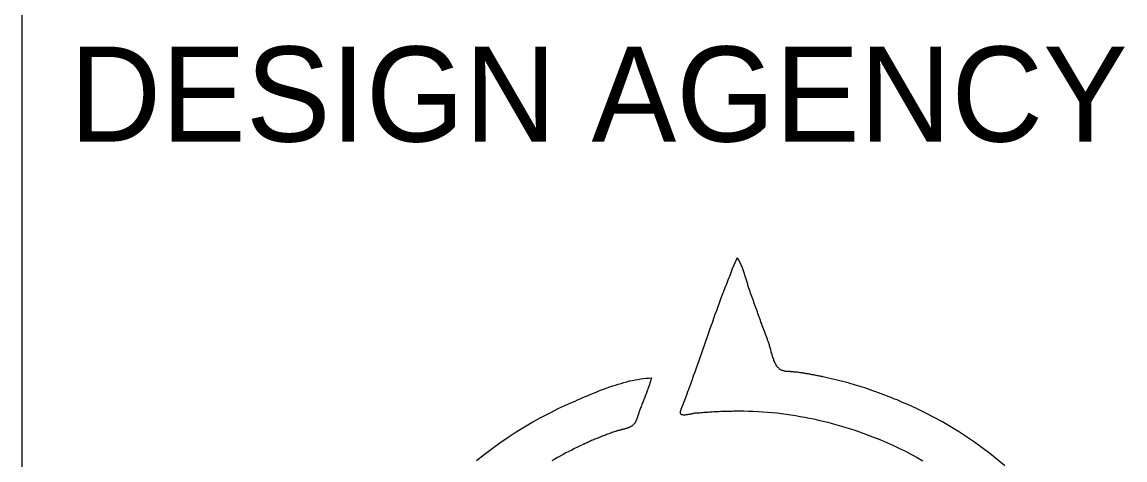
# Model space of a CAD drawing. Extents: x -1.1 to 34, y 0 to 22.
# Drawn here: x 32 to 33.162, y 4.015 to 4.476 of the extents above; entities that cross this region are included whole.
import ezdxf

# ---------------------------------------------------------------- set-up
doc = ezdxf.new("R2010")
doc.units = 0
doc.layers.add('BR_X_SV_Abut', color=7, linetype='Continuous')
doc.layers.add('RW_X_CL', color=7, linetype='Continuous')

msp = doc.modelspace()

# ---------------------------------------------------------------- linework, layer by layer
at = {"layer": 'BR_X_SV_Abut'}
for points in [[(32.7532, 4.2277), (32.7515, 4.2238), (32.7498, 4.2199), (32.7481, 4.216), (32.7466, 4.212), (32.745, 4.208), (32.7434, 4.2041), (32.7418, 4.2001), (32.7403, 4.1961), (32.7387, 4.1921), (32.7372, 4.1881), (32.7357, 4.1841), (32.7342, 4.1801), (32.7328, 4.176), (32.7313, 4.172), (32.7298, 4.168), (32.7284, 4.1639), (32.7271, 4.1599), (32.7256, 4.1558), (32.7241, 4.1518), (32.7227, 4.1478), (32.7214, 4.1436), (32.7199, 4.1396), (32.7184, 4.1355), (32.7171, 4.1315), (32.7157, 4.1275), (32.7142, 4.1235), (32.7129, 4.1194), (32.7114, 4.1154), (32.71, 4.1114), (32.7085, 4.1074), (32.707, 4.1035)], [(32.7656, 4.1959), (32.7652, 4.1969), (32.7649, 4.1978), (32.7646, 4.1988), (32.7643, 4.1998), (32.764, 4.2009), (32.7637, 4.202), (32.7633, 4.2031), (32.7631, 4.2041), (32.7627, 4.2051), (32.7623, 4.2063), (32.7621, 4.2074), (32.7617, 4.2085), (32.7614, 4.2096), (32.761, 4.2107), (32.7606, 4.2118), (32.7603, 4.2129), (32.7599, 4.214), (32.7595, 4.2151), (32.7592, 4.2161), (32.7587, 4.2172), (32.7583, 4.2182), (32.7578, 4.2193), (32.7575, 4.2203), (32.757, 4.2214), (32.7565, 4.2223), (32.756, 4.2233), (32.7555, 4.2242), (32.7549, 4.2251), (32.7545, 4.226), (32.7538, 4.2268), (32.7532, 4.2277)], [(32.7856, 4.1404), (32.785, 4.1422), (32.7844, 4.144), (32.7837, 4.1457), (32.7831, 4.1475), (32.7823, 4.1493), (32.7817, 4.1512), (32.781, 4.1529), (32.7804, 4.1547), (32.7797, 4.1565), (32.7791, 4.1582), (32.7783, 4.16), (32.7777, 4.1618), (32.777, 4.1637), (32.7764, 4.1654), (32.7758, 4.1672), (32.7751, 4.169), (32.7745, 4.1708), (32.7739, 4.1725), (32.7731, 4.1743), (32.7725, 4.1761), (32.7719, 4.178), (32.7712, 4.1797), (32.7706, 4.1815), (32.77, 4.1833), (32.7694, 4.1851), (32.7686, 4.1869), (32.768, 4.1886), (32.7674, 4.1904), (32.7668, 4.1923), (32.7662, 4.1941), (32.7656, 4.1959)], [(32.7979, 4.1106), (32.7973, 4.1112), (32.7966, 4.1118), (32.796, 4.1124), (32.7954, 4.1131), (32.7949, 4.1138), (32.7943, 4.1147), (32.7939, 4.1156), (32.7934, 4.1165), (32.7929, 4.1175), (32.7925, 4.1186), (32.792, 4.1195), (32.7917, 4.1206), (32.7913, 4.1217), (32.7908, 4.1228), (32.7905, 4.1239), (32.7901, 4.1251), (32.7899, 4.1262), (32.7895, 4.1274), (32.7891, 4.1285), (32.7889, 4.1296), (32.7885, 4.1308), (32.7882, 4.1319), (32.7879, 4.133), (32.7877, 4.1341), (32.7873, 4.135), (32.7871, 4.136), (32.7868, 4.137), (32.7865, 4.138), (32.7862, 4.1388), (32.786, 4.1396), (32.7856, 4.1404)], [(32.5747, 4.0736), (32.5772, 4.0747), (32.5799, 4.0759), (32.5825, 4.077), (32.5852, 4.0782), (32.5879, 4.0794), (32.5907, 4.0806), (32.5934, 4.0818), (32.5962, 4.0829), (32.599, 4.0841), (32.6018, 4.0853), (32.6047, 4.0864), (32.6075, 4.0876), (32.6104, 4.0887), (32.6133, 4.0898), (32.6162, 4.0909), (32.6192, 4.0919), (32.6221, 4.093), (32.6251, 4.0938), (32.628, 4.0948), (32.6309, 4.0956), (32.6338, 4.0965), (32.6369, 4.0973), (32.6398, 4.0981), (32.6427, 4.0987), (32.6456, 4.0993), (32.6485, 4.0998), (32.6514, 4.1002), (32.6543, 4.1007), (32.6572, 4.101), (32.6601, 4.1012), (32.6629, 4.1015)], [(32.6629, 4.1015), (32.6626, 4.1002), (32.6623, 4.0992), (32.6619, 4.0979), (32.6616, 4.0969), (32.6612, 4.0958), (32.6609, 4.0945), (32.6605, 4.0935), (32.6601, 4.0922), (32.6596, 4.0912), (32.6593, 4.0901), (32.6589, 4.0888), (32.6584, 4.0878), (32.6581, 4.0867), (32.6576, 4.0856), (32.6572, 4.0844), (32.6567, 4.0833), (32.6564, 4.0822), (32.6559, 4.0811), (32.6555, 4.0799), (32.655, 4.0788), (32.6546, 4.0777), (32.6542, 4.0766), (32.6537, 4.0754), (32.6532, 4.0743), (32.6529, 4.0732), (32.6524, 4.0721), (32.652, 4.071), (32.6515, 4.0698), (32.6512, 4.0687), (32.6507, 4.0676), (32.6503, 4.0665)], [(32.707, 4.1035), (32.7067, 4.1025), (32.7063, 4.1016), (32.7061, 4.1006), (32.7057, 4.0996), (32.7054, 4.0987), (32.705, 4.0977), (32.7046, 4.0967), (32.7043, 4.0958), (32.7039, 4.0948), (32.7037, 4.0938), (32.7033, 4.0928), (32.7029, 4.092), (32.7026, 4.091), (32.7022, 4.0901), (32.7018, 4.0891), (32.7015, 4.0881), (32.7011, 4.0872), (32.7007, 4.0862), (32.7005, 4.0852), (32.7001, 4.0842), (32.6998, 4.0833), (32.6994, 4.0823), (32.699, 4.0813), (32.6987, 4.0804), (32.6983, 4.0795), (32.698, 4.0785), (32.6976, 4.0776), (32.6972, 4.0766), (32.6969, 4.0756), (32.6965, 4.0747), (32.6963, 4.0737)], [(32.8139, 4.1075), (32.8134, 4.1075), (32.8129, 4.1076), (32.8124, 4.1076), (32.8119, 4.1076), (32.8114, 4.1078), (32.8108, 4.1078), (32.8103, 4.1078), (32.8097, 4.1078), (32.8093, 4.1079), (32.8086, 4.1079), (32.808, 4.1079), (32.8076, 4.1079), (32.807, 4.108), (32.8063, 4.108), (32.8059, 4.1081), (32.8053, 4.1081), (32.8046, 4.1082), (32.8042, 4.1082), (32.8036, 4.1084), (32.8031, 4.1085), (32.8025, 4.1086), (32.802, 4.1087), (32.8015, 4.1089), (32.8009, 4.109), (32.8004, 4.1092), (32.7999, 4.1093), (32.7996, 4.1096), (32.7991, 4.1098), (32.7986, 4.1101), (32.7982, 4.1103), (32.7979, 4.1106)], [(32.8436, 4.1024), (32.8426, 4.1027), (32.8417, 4.1028), (32.8408, 4.103), (32.8398, 4.1033), (32.8388, 4.1034), (32.8379, 4.1036), (32.8369, 4.1038), (32.8359, 4.104), (32.835, 4.1041), (32.8341, 4.1044), (32.8331, 4.1045), (32.8322, 4.1047), (32.8312, 4.1049), (32.8302, 4.1051), (32.8293, 4.1052), (32.8283, 4.1055), (32.8273, 4.1056), (32.8263, 4.1057), (32.8254, 4.1059), (32.8244, 4.1061), (32.8234, 4.1062), (32.8225, 4.1063), (32.8215, 4.1065), (32.8205, 4.1067), (32.8196, 4.1068), (32.8186, 4.1069), (32.8177, 4.107), (32.8168, 4.1072), (32.8158, 4.1073), (32.8148, 4.1074), (32.8139, 4.1075)], [(32.9329, 4.0732), (32.9301, 4.0744), (32.9273, 4.0756), (32.9246, 4.0768), (32.9216, 4.0781), (32.9189, 4.0791), (32.9161, 4.0802), (32.9133, 4.0815), (32.9104, 4.0825), (32.9076, 4.0835), (32.9048, 4.0846), (32.9019, 4.0857), (32.8991, 4.0867), (32.8962, 4.0878), (32.8933, 4.0887), (32.8905, 4.0897), (32.8876, 4.0907), (32.8847, 4.0915), (32.8818, 4.0925), (32.8788, 4.0933), (32.8759, 4.0943), (32.873, 4.0952), (32.8701, 4.096), (32.8672, 4.0967), (32.8643, 4.0976), (32.8614, 4.0983), (32.8584, 4.099), (32.8554, 4.0998), (32.8525, 4.1005), (32.8495, 4.1012), (32.8466, 4.1018), (32.8436, 4.1024)], [(32.4788, 4.0143), (32.4868, 4.0207), (32.495, 4.0269), (32.5034, 4.033), (32.5119, 4.0388), (32.5205, 4.0445), (32.5292, 4.0498), (32.538, 4.055), (32.547, 4.06), (32.5561, 4.0647), (32.5653, 4.0693), (32.5747, 4.0736)], [(32.6503, 4.0665), (32.6501, 4.0661), (32.6499, 4.0656), (32.6498, 4.0652), (32.6496, 4.0647), (32.6495, 4.0642), (32.6493, 4.0638), (32.6492, 4.0631), (32.649, 4.0627), (32.6489, 4.0622), (32.6487, 4.0617), (32.6485, 4.0611), (32.6484, 4.0606), (32.6481, 4.0601), (32.648, 4.0595), (32.6478, 4.059), (32.6476, 4.0585), (32.6474, 4.0579), (32.6473, 4.0574), (32.647, 4.057), (32.6468, 4.0565), (32.6466, 4.056), (32.6463, 4.0555), (32.6461, 4.055), (32.6458, 4.0545), (32.6456, 4.0542), (32.6453, 4.0537), (32.6451, 4.0533), (32.6447, 4.053), (32.6445, 4.0525), (32.6441, 4.0521), (32.6438, 4.0519)], [(32.6963, 4.0737), (32.6961, 4.0735), (32.696, 4.0732), (32.6959, 4.073), (32.6958, 4.0727), (32.6957, 4.0724), (32.6955, 4.0721), (32.6954, 4.0718), (32.6952, 4.0714), (32.695, 4.071), (32.6949, 4.0707), (32.6947, 4.0703), (32.6946, 4.0699), (32.6944, 4.0696), (32.6942, 4.0691), (32.6941, 4.0687), (32.694, 4.0684), (32.6938, 4.068), (32.6937, 4.0675), (32.6936, 4.0671), (32.6935, 4.0668), (32.6935, 4.0664), (32.6933, 4.0661), (32.6933, 4.0657), (32.6932, 4.0653), (32.6932, 4.065), (32.6932, 4.0647), (32.6933, 4.0644), (32.6933, 4.0641), (32.6935, 4.0639), (32.6936, 4.0636), (32.6937, 4.0634)], [(32.7091, 4.0644), (32.7106, 4.0645), (32.7121, 4.0646), (32.7136, 4.0647), (32.7151, 4.0648), (32.7166, 4.065), (32.7181, 4.0651), (32.7195, 4.0652), (32.721, 4.0653), (32.7226, 4.0654), (32.724, 4.0656), (32.7255, 4.0657), (32.7269, 4.0657), (32.7285, 4.0658), (32.73, 4.0659), (32.7314, 4.0659), (32.7329, 4.0661), (32.7344, 4.0661), (32.7359, 4.0662), (32.7374, 4.0662), (32.7388, 4.0663), (32.7404, 4.0663), (32.7418, 4.0663), (32.7433, 4.0664), (32.7449, 4.0664), (32.7463, 4.0664), (32.7478, 4.0664), (32.7494, 4.0665), (32.7508, 4.0665), (32.7523, 4.0665), (32.7538, 4.0665), (32.7553, 4.0665)], [(32.7553, 4.0665), (32.7603, 4.0665), (32.7652, 4.0664), (32.7702, 4.0662), (32.7752, 4.0659), (32.7802, 4.0657), (32.785, 4.0653), (32.79, 4.0648), (32.7949, 4.0644), (32.7999, 4.0638), (32.8048, 4.0631), (32.8097, 4.0624), (32.8146, 4.0617), (32.8196, 4.0608), (32.8244, 4.06), (32.8293, 4.059), (32.8341, 4.0581), (32.839, 4.057), (32.8438, 4.0558), (32.8487, 4.0547), (32.8534, 4.0533), (32.8582, 4.052), (32.863, 4.0507), (32.8678, 4.0492), (32.8725, 4.0477), (32.8773, 4.0462), (32.882, 4.0446), (32.8866, 4.0429), (32.8913, 4.0412), (32.8959, 4.0394), (32.9005, 4.0376), (32.9052, 4.0357)], [(33.0351, 4.0088), (33.0272, 4.0154), (33.0194, 4.0217), (33.0112, 4.0277), (33.0031, 4.0337), (32.9947, 4.0394), (32.9863, 4.045), (32.9777, 4.0503), (32.9689, 4.0553), (32.9601, 4.0601), (32.9511, 4.0647), (32.942, 4.0691), (32.9329, 4.0732)], [(32.6937, 4.0634), (32.694, 4.0633), (32.6942, 4.063), (32.6946, 4.0629), (32.6949, 4.0628), (32.6954, 4.0627), (32.6958, 4.0627), (32.6963, 4.0625), (32.6967, 4.0625), (32.6973, 4.0625), (32.6978, 4.0625), (32.6984, 4.0625), (32.699, 4.0627), (32.6997, 4.0627), (32.7003, 4.0628), (32.7009, 4.0629), (32.7015, 4.063), (32.7021, 4.063), (32.7027, 4.0631), (32.7033, 4.0633), (32.7039, 4.0634), (32.7045, 4.0635), (32.705, 4.0636), (32.7056, 4.0638), (32.7062, 4.0639), (32.7067, 4.064), (32.7072, 4.0641), (32.7077, 4.0641), (32.708, 4.0642), (32.7085, 4.0644), (32.7087, 4.0644), (32.7091, 4.0644)], [(32.6259, 4.0453), (32.6248, 4.045), (32.6236, 4.0445), (32.6225, 4.0441), (32.6213, 4.0437), (32.6202, 4.0433), (32.6192, 4.0429), (32.6179, 4.0425), (32.6168, 4.0421), (32.6156, 4.0417), (32.6145, 4.0412), (32.6135, 4.0407), (32.6122, 4.0404), (32.6111, 4.0399), (32.6101, 4.0394), (32.6088, 4.039), (32.6078, 4.0385), (32.6067, 4.038), (32.6055, 4.0376), (32.6044, 4.0372), (32.6033, 4.0367), (32.6022, 4.0362), (32.601, 4.0357), (32.5999, 4.0353), (32.5988, 4.0348), (32.5977, 4.0343), (32.5966, 4.0338), (32.5955, 4.0333), (32.5944, 4.0328), (32.5932, 4.0324), (32.5921, 4.0317), (32.591, 4.0313)], [(32.6438, 4.0519), (32.6434, 4.0515), (32.6429, 4.0511), (32.6424, 4.0508), (32.6421, 4.0505), (32.6415, 4.0502), (32.641, 4.0499), (32.6405, 4.0497), (32.6399, 4.0493), (32.6393, 4.0491), (32.6387, 4.0488), (32.6381, 4.0487), (32.6375, 4.0485), (32.6369, 4.0482), (32.6362, 4.0481), (32.6356, 4.0479), (32.635, 4.0476), (32.6343, 4.0475), (32.6337, 4.0474), (32.6331, 4.0471), (32.6324, 4.047), (32.6318, 4.0469), (32.6312, 4.0467), (32.6305, 4.0465), (32.6299, 4.0464), (32.6293, 4.0463), (32.6287, 4.0461), (32.6281, 4.0459), (32.6275, 4.0458), (32.627, 4.0456), (32.6264, 4.0454), (32.6259, 4.0453)], [(32.591, 4.0313), (32.588, 4.0299), (32.585, 4.0284), (32.5819, 4.0269), (32.5789, 4.0254), (32.5759, 4.0239), (32.5728, 4.0223), (32.5698, 4.0207), (32.5669, 4.0191), (32.5639, 4.0174), (32.561, 4.0157), (32.558, 4.014)], [(32.9052, 4.0357), (32.9116, 4.033), (32.9179, 4.0302), (32.9242, 4.0271), (32.9305, 4.0241), (32.9367, 4.0208), (32.9427, 4.0174), (32.9488, 4.014)]]:
    msp.add_lwpolyline(points, dxfattribs=at)
at = {"layer": 'RW_X_CL'}
msp.add_line((32, 0.5), (32, 21.5), dxfattribs=at)

# ---------------------------------------------------------------- texts
at = {"layer": 'BR_X_SV_Abut'}
msp.add_text('DESIGN AGENCY', height=0.1, dxfattribs=at).set_placement((32.05, 4.35))

doc.saveas('drawing.dxf')
